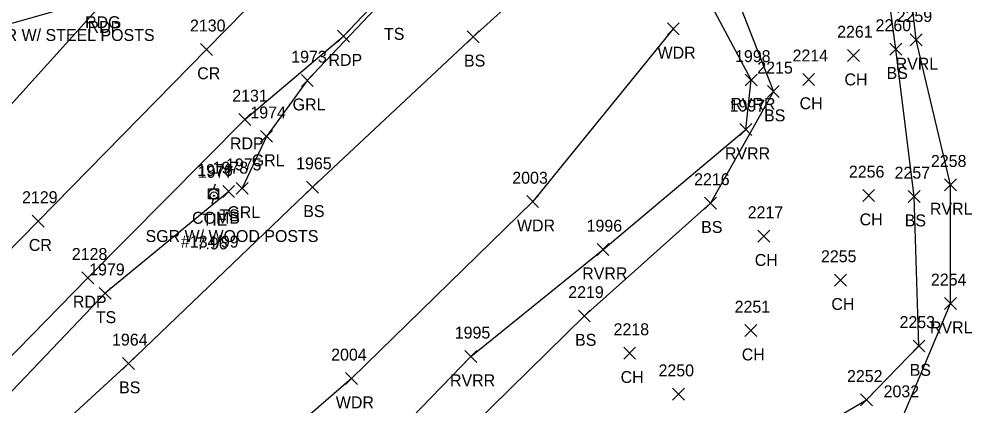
# Model space of a CAD drawing. Extents: x 1633660 to 1636532, y 388643 to 392631.
# Drawn here: x 1634668.1 to 1634827.8, y 389113.6 to 389178.4 of the extents above; entities that cross this region are included whole.
import ezdxf

# ---------------------------------------------------------------- set-up
doc = ezdxf.new("R2010")
doc.units = 0
for name, color, linetype in [('C_A', 7, 'Continuous'), ('C_C', 7, 'Continuous'), ('C_I', 7, 'Continuous'), ('CBP', 7, 'Continuous'), ('L_A', 7, 'Continuous'), ('L_I', 7, 'Continuous'), ('L_TIC', 7, 'Continuous'), ('LAWA', 7, 'Continuous'), ('LAWE', 7, 'Continuous'), ('LELB', 7, 'Continuous'), ('P_A', 7, 'Continuous'), ('P_I', 7, 'Continuous'), ('P_TIC', 7, 'Continuous'), ('PET', 7, 'Continuous'), ('PEU', 7, 'Continuous'), ('PRC', 7, 'Continuous'), ('R_A', 7, 'Continuous'), ('R_C', 7, 'Continuous'), ('R_I', 7, 'Continuous'), ('R_TIC', 7, 'Continuous'), ('RGR', 7, 'Continuous'), ('U_A', 7, 'Continuous'), ('U_C', 7, 'Continuous'), ('U_I', 7, 'Continuous'), ('UP', 7, 'Continuous')]:
    doc.layers.add(name, color=color, linetype=linetype)

msp = doc.modelspace()

# ---------------------------------------------------------------- linework, layer by layer
at = {"layer": 'CBP'}
for radius in [0.625, 0.0833]:
    msp.add_circle((1634700.75, 389148.83), radius, dxfattribs=at)
at = {"layer": 'L_TIC'}
for points in [[(1634776.74, 389175.81), (1634778.74, 389177.81)], [(1634778.74, 389175.81), (1634776.74, 389177.81)], [(1634743.21, 389174.48), (1634745.21, 389176.48)], [(1634745.21, 389174.48), (1634743.21, 389176.48)], [(1634817.45, 389173.95), (1634819.45, 389175.95)], [(1634819.45, 389173.95), (1634817.45, 389175.95)], [(1634806.94, 389171.32), (1634808.94, 389173.32)], [(1634808.94, 389171.32), (1634806.94, 389173.32)], [(1634814.05, 389172.41), (1634816.05, 389174.41)], [(1634816.05, 389172.41), (1634814.05, 389174.41)], [(1634789.78, 389167.23), (1634791.78, 389169.23)], [(1634791.78, 389167.23), (1634789.78, 389169.23)], [(1634799.43, 389167.33), (1634801.43, 389169.33)], [(1634801.43, 389167.33), (1634799.43, 389169.33)], [(1634793.51, 389165.3), (1634795.51, 389167.3)], [(1634795.51, 389165.3), (1634793.51, 389167.3)], [(1634788.88, 389158.93), (1634790.88, 389160.93)], [(1634790.88, 389158.93), (1634788.88, 389160.93)], [(1634702.21, 389148.54), (1634704.21, 389150.54)], [(1634704.21, 389148.54), (1634702.21, 389150.54)], [(1634716.26, 389149.25), (1634718.26, 389151.25)], [(1634718.26, 389149.25), (1634716.26, 389151.25)], [(1634823.18, 389149.65), (1634825.18, 389151.65)], [(1634825.18, 389149.65), (1634823.18, 389151.65)], [(1634809.48, 389147.86), (1634811.48, 389149.86)], [(1634811.48, 389147.86), (1634809.48, 389149.86)], [(1634817.09, 389147.69), (1634819.09, 389149.69)], [(1634819.09, 389147.69), (1634817.09, 389149.69)], [(1634753.17, 389146.84), (1634755.17, 389148.84)], [(1634755.17, 389146.84), (1634753.17, 389148.84)], [(1634782.97, 389146.59), (1634784.97, 389148.59)], [(1634784.97, 389146.59), (1634782.97, 389148.59)], [(1634791.9, 389141.06), (1634793.9, 389143.06)], [(1634793.9, 389141.06), (1634791.9, 389143.06)], [(1634764.96, 389138.81), (1634766.96, 389140.81)], [(1634766.96, 389138.81), (1634764.96, 389140.81)], [(1634804.75, 389133.68), (1634806.75, 389135.68)], [(1634806.75, 389133.68), (1634804.75, 389135.68)], [(1634681.53, 389131.47), (1634683.53, 389133.47)], [(1634683.53, 389131.47), (1634681.53, 389133.47)], [(1634823.18, 389129.77), (1634825.18, 389131.77)], [(1634825.18, 389129.77), (1634823.18, 389131.77)], [(1634761.83, 389127.67), (1634763.83, 389129.67)], [(1634763.83, 389127.67), (1634761.83, 389129.67)], [(1634789.72, 389125.22), (1634791.72, 389127.22)], [(1634791.72, 389125.22), (1634789.72, 389127.22)], [(1634769.43, 389121.44), (1634771.43, 389123.44)], [(1634771.43, 389121.44), (1634769.43, 389123.44)], [(1634817.92, 389122.64), (1634819.92, 389124.64)], [(1634819.92, 389122.64), (1634817.92, 389124.64)], [(1634742.8, 389120.88), (1634744.8, 389122.88)], [(1634744.8, 389120.88), (1634742.8, 389122.88)], [(1634685.4, 389119.7), (1634687.4, 389121.7)], [(1634687.4, 389119.7), (1634685.4, 389121.7)], [(1634722.8, 389117.19), (1634724.8, 389119.19)], [(1634724.8, 389117.19), (1634722.8, 389119.19)], [(1634777.6, 389114.55), (1634779.6, 389116.55)], [(1634779.6, 389114.55), (1634777.6, 389116.55)], [(1634809.12, 389113.6), (1634811.12, 389115.6)], [(1634811.12, 389113.6), (1634809.12, 389115.6)]]:
    msp.add_lwpolyline(points, dxfattribs=at)
at = {"layer": 'LAWA'}
msp.add_lwpolyline([(1634777.74, 389176.81), (1634754.17, 389147.84), (1634723.8, 389118.19), (1634689.85, 389088.67), (1634673.22, 389058.41), (1634669.47, 389042.78), (1634646.69, 389025.62), (1634627.54, 389002.43), (1634610.06, 388987.13), (1634597.62, 388969.61)], dxfattribs=at)
at = {"layer": 'LAWE'}
for points in [[(1634485.27, 388945.87), (1634504.2, 388941.24), (1634525.53, 388940.73), (1634548.51, 388932.94), (1634584.66, 388920), (1634598.75, 388914.41), (1634618.8, 388928.88), (1634638.3, 388944.91), (1634660.99, 388957.08), (1634677.58, 388983.24), (1634696.95, 389006.4), (1634707.36, 389033.31), (1634727.93, 389056.72), (1634749.89, 389078.7), (1634762.92, 389095.06), (1634797.9, 389102.54), (1634816.33, 389112.04), (1634824.18, 389130.77), (1634824.18, 389150.65), (1634818.45, 389174.95), (1634815.05, 389205.92), (1634802.11, 389220.82), (1634788.76, 389226.82)], [(1634520.43, 388972.83), (1634529.58, 388972.39), (1634557.27, 388957.37), (1634580.07, 388955.67), (1634596.48, 388954.83), (1634611.77, 388964.29), (1634628.48, 388986.24), (1634647.88, 389006.91), (1634658.84, 389024.3), (1634672.7, 389044.33), (1634690.56, 389064.6), (1634720.63, 389097.89), (1634743.8, 389121.88), (1634765.96, 389139.81), (1634789.88, 389159.93), (1634790.78, 389168.23), (1634779.52, 389189.43), (1634780.72, 389197.89), (1634770.08, 389207.77)]]:
    msp.add_lwpolyline(points, dxfattribs=at)
at = {"layer": 'LELB'}
for points in [[(1634633.7, 388947.02), (1634652.59, 388956.59), (1634671.2, 388984.13), (1634685.4, 389000.21), (1634693.63, 389014.81), (1634704.34, 389035.4), (1634725.63, 389062.25), (1634746.9, 389081.24), (1634759.28, 389096.89), (1634788.69, 389102.01), (1634810.12, 389114.6), (1634818.92, 389123.64), (1634818.09, 389148.69), (1634815.05, 389173.41), (1634811.19, 389202.43), (1634801.32, 389217.95), (1634788.87, 389224.41)], [(1634776.58, 389212.05), (1634784.35, 389200.64), (1634784.71, 389191.5), (1634794.51, 389166.3), (1634783.97, 389147.59), (1634762.83, 389128.67), (1634740.89, 389107.13), (1634715.47, 389080.9), (1634695.42, 389057.67), (1634668.32, 389027.16), (1634645.64, 388997.18), (1634619.55, 388957.69)], [(1634531.18, 388975.28), (1634550.04, 388993.84), (1634582.85, 389016.58), (1634590.99, 389033.59), (1634624.25, 389062.77), (1634653.38, 389090.44), (1634686.4, 389120.7), (1634717.26, 389150.25), (1634744.21, 389175.48), (1634771.92, 389200.56)], [(1634703.21, 389149.54), (1634682.53, 389132.47), (1634655.74, 389104.45), (1634622.93, 389072.78), (1634589.92, 389040.08), (1634578.99, 389022.4), (1634560.52, 389008.32), (1634535.52, 388993.05), (1634511.92, 388973.77)]]:
    msp.add_lwpolyline(points, dxfattribs=at)
at = {"layer": 'P_TIC'}
for points in [[(1634721.45, 389174.59), (1634723.45, 389176.59)], [(1634723.45, 389174.59), (1634721.45, 389176.59)], [(1634698.51, 389172.36), (1634700.51, 389174.36)], [(1634700.51, 389172.36), (1634698.51, 389174.36)], [(1634704.94, 389160.6), (1634706.94, 389162.6)], [(1634706.94, 389160.6), (1634704.94, 389162.6)], [(1634670.28, 389143.58), (1634672.28, 389145.58)], [(1634672.28, 389143.58), (1634670.28, 389145.58)], [(1634678.61, 389134.06), (1634680.61, 389136.06)], [(1634680.61, 389134.06), (1634678.61, 389136.06)]]:
    msp.add_lwpolyline(points, dxfattribs=at)
at = {"layer": 'PET'}
msp.add_lwpolyline([(1634682.08, 389181.1), (1634650.7, 389146.38), (1634620.25, 389115.23), (1634604.63, 389098.3), (1634579.1, 389070.12), (1634546.56, 389039.3), (1634509.68, 389006.46), (1634474.11, 388976.77), (1634488.61, 388975.18), (1634504.36, 388973.04), (1634532.03, 388994.36), (1634563.21, 389020.04), (1634596.33, 389051.02), (1634641.93, 389096.55), (1634679.61, 389135.06), (1634705.94, 389161.6), (1634722.45, 389175.59), (1634749.3, 389203.85), (1634763.45, 389218.45), (1634753.18, 389229.52), (1634742.76, 389239.64), (1634704.36, 389200.19), (1634691.63, 389189.01)], dxfattribs=at)
at = {"layer": 'PEU'}
msp.add_lwpolyline([(1634681.66, 389181.92), (1634655.28, 389174.45), (1634621.42, 389148.64), (1634596.29, 389137.43), (1634576.33, 389130.43), (1634529, 389119.71), (1634497.86, 389117.98)], dxfattribs=at)
at = {"layer": 'PRC'}
msp.add_lwpolyline([(1634489.59, 388976.11), (1634524.5, 389003.94), (1634553.65, 389029.27), (1634589.65, 389062.97), (1634628.75, 389101.27), (1634671.28, 389144.58), (1634699.51, 389173.36), (1634712.64, 389186.75), (1634739.32, 389214.16), (1634752.84, 389228.98)], dxfattribs=at)
at = {"layer": 'R_TIC'}
for points in [[(1634715.39, 389167.13), (1634717.39, 389169.13)], [(1634717.39, 389167.13), (1634715.39, 389169.13)], [(1634708.54, 389157.78), (1634710.54, 389159.78)], [(1634710.54, 389157.78), (1634708.54, 389159.78)], [(1634704.45, 389149.07), (1634706.45, 389151.07)], [(1634706.45, 389149.07), (1634704.45, 389151.07)]]:
    msp.add_lwpolyline(points, dxfattribs=at)
at = {"layer": 'RGR'}
msp.add_lwpolyline([(1634762.74, 389216.64), (1634741.24, 389194.43), (1634716.39, 389168.13), (1634709.54, 389158.78), (1634705.45, 389150.07)], dxfattribs=at)
at = {"layer": 'UP'}
for p, q in [((1634700.94, 389150.79), (1634700.69, 389149.96)), ((1634699.85, 389148.29), (1634699.85, 389149.96)), ((1634699.85, 389149.96), (1634701.52, 389149.96)), ((1634700.69, 389149.13), (1634700.69, 389149.13)), ((1634701.52, 389149.96), (1634701.52, 389148.29)), ((1634701.52, 389148.29), (1634699.85, 389148.29)), ((1634700.44, 389147.46), (1634700.69, 389148.29))]:
    msp.add_line(p, q, dxfattribs=at)
msp.add_circle((1634700.69, 389149.13), 0.833, dxfattribs=at)

# ---------------------------------------------------------------- texts
at = {"layer": 'C_A'}
msp.add_text('TIE', height=2, dxfattribs=at).set_placement((1634698.83, 389143.83))
at = {"layer": 'C_C'}
msp.add_text('7.96', height=2, dxfattribs=at).set_placement((1634697.84, 389139.83))
at = {"layer": 'C_I'}
msp.add_text('1977', height=2, dxfattribs=at).set_placement((1634698.05, 389151.83))
at = {"layer": 'L_A'}
for s, p in [('TS', (1634729.25, 389174.96)), ('WDR', (1634775.1, 389171.81)), ('BS', (1634742.66, 389170.48)), ('RVRL', (1634815.01, 389169.95)), ('BS', (1634813.49, 389168.41)), ('CH', (1634806.43, 389167.32)), ('RVRR', (1634787.29, 389163.23)), ('CH', (1634798.91, 389163.33)), ('BS', (1634792.95, 389161.3)), ('RVRR', (1634786.39, 389154.93)), ('RVRL', (1634820.75, 389145.65)), ('TS', (1634701.62, 389144.54)), ('BS', (1634715.71, 389145.25)), ('CH', (1634808.97, 389143.86)), ('WDR', (1634751.53, 389142.84)), ('BS', (1634782.41, 389142.59)), ('BS', (1634816.53, 389143.69)), ('CH', (1634791.39, 389137.06)), ('RVRR', (1634762.47, 389134.81)), ('CH', (1634804.23, 389129.68)), ('TS', (1634680.94, 389127.47)), ('RVRL', (1634820.75, 389125.77)), ('BS', (1634761.27, 389123.67)), ('CH', (1634789.21, 389121.22)), ('BS', (1634817.36, 389118.64)), ('RVRR', (1634740.31, 389116.88)), ('CH', (1634768.91, 389117.44)), ('BS', (1634684.84, 389115.7)), ('WDR', (1634721.17, 389113.19))]:
    msp.add_text(s, height=2, dxfattribs=at).set_placement(p)
at = {"layer": 'L_I'}
for s, p in [('2259', (1634815.18, 389177.95)), ('2260', (1634811.65, 389176.41)), ('2261', (1634805.2, 389175.32)), ('1998', (1634788.09, 389171.23)), ('2214', (1634797.73, 389171.33)), ('2215', (1634791.82, 389169.3)), ('1997', (1634787.18, 389162.93)), ('2258', (1634820.92, 389153.65)), ('1978', (1634700.52, 389152.54)), ('1965', (1634714.52, 389153.25)), ('2256', (1634807.17, 389151.86)), ('2003', (1634750.75, 389150.84)), ('2216', (1634781.23, 389150.59)), ('2257', (1634814.83, 389151.69)), ('2217', (1634790.21, 389145.06)), ('1996', (1634763.21, 389142.81)), ('2255', (1634802.49, 389137.68)), ('1979', (1634679.83, 389135.47)), ('2254', (1634820.92, 389133.77)), ('2219', (1634760.13, 389131.67)), ('2251', (1634788.02, 389129.22)), ('2253', (1634815.66, 389126.64)), ('1995', (1634741.11, 389124.88)), ('2218', (1634767.73, 389125.44)), ('1964', (1634683.66, 389123.7)), ('2004', (1634720.39, 389121.19)), ('2250', (1634775.26, 389118.55)), ('2252', (1634806.86, 389117.6)), ('2032', (1634812.99, 389115.04))]:
    msp.add_text(s, height=2, dxfattribs=at).set_placement(p)
at = {"layer": 'P_A'}
for s, p in [('RDG', (1634679.14, 389176.92)), ('RDP', (1634679.57, 389176.1)), ('RDP', (1634719.94, 389170.59)), ('CR', (1634697.94, 389168.36)), ('RDP', (1634703.43, 389156.6)), ('CR', (1634669.71, 389139.58)), ('RDP', (1634677.1, 389130.06))]:
    msp.add_text(s, height=2, dxfattribs=at).set_placement(p)
at = {"layer": 'P_I'}
for s, p in [('2130', (1634696.73, 389176.36)), ('2131', (1634703.81, 389164.6)), ('2129', (1634668.58, 389147.58)), ('2128', (1634676.92, 389138.06))]:
    msp.add_text(s, height=2, dxfattribs=at).set_placement(p)
at = {"layer": 'R_A'}
for p in [(1634713.93, 389163.13), (1634707.08, 389153.78), (1634703, 389145.07)]:
    msp.add_text('GRL', height=2, dxfattribs=at).set_placement(p)
at = {"layer": 'R_C'}
for s, p in [('SGR W/ STEEL POSTS', (1634661.96, 389174.77)), ('SGR W/ WOOD POSTS', (1634689.28, 389141.07))]:
    msp.add_text(s, height=2, dxfattribs=at).set_placement(p)
at = {"layer": 'R_I'}
for s, p in [('1973', (1634713.7, 389171.13)), ('1974', (1634706.85, 389161.78)), ('1975', (1634702.76, 389153.07))]:
    msp.add_text(s, height=2, dxfattribs=at).set_placement(p)
at = {"layer": 'U_A'}
msp.add_text('COMB', height=2, dxfattribs=at).set_placement((1634697.07, 389144.13))
at = {"layer": 'U_C'}
msp.add_text('#134/99', height=2, dxfattribs=at).set_placement((1634695.21, 389140.13))
at = {"layer": 'U_I'}
msp.add_text('1976', height=2, dxfattribs=at).set_placement((1634697.94, 389152.13))

doc.saveas('drawing.dxf')
